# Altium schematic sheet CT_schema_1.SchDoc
size 395 x 258 mm
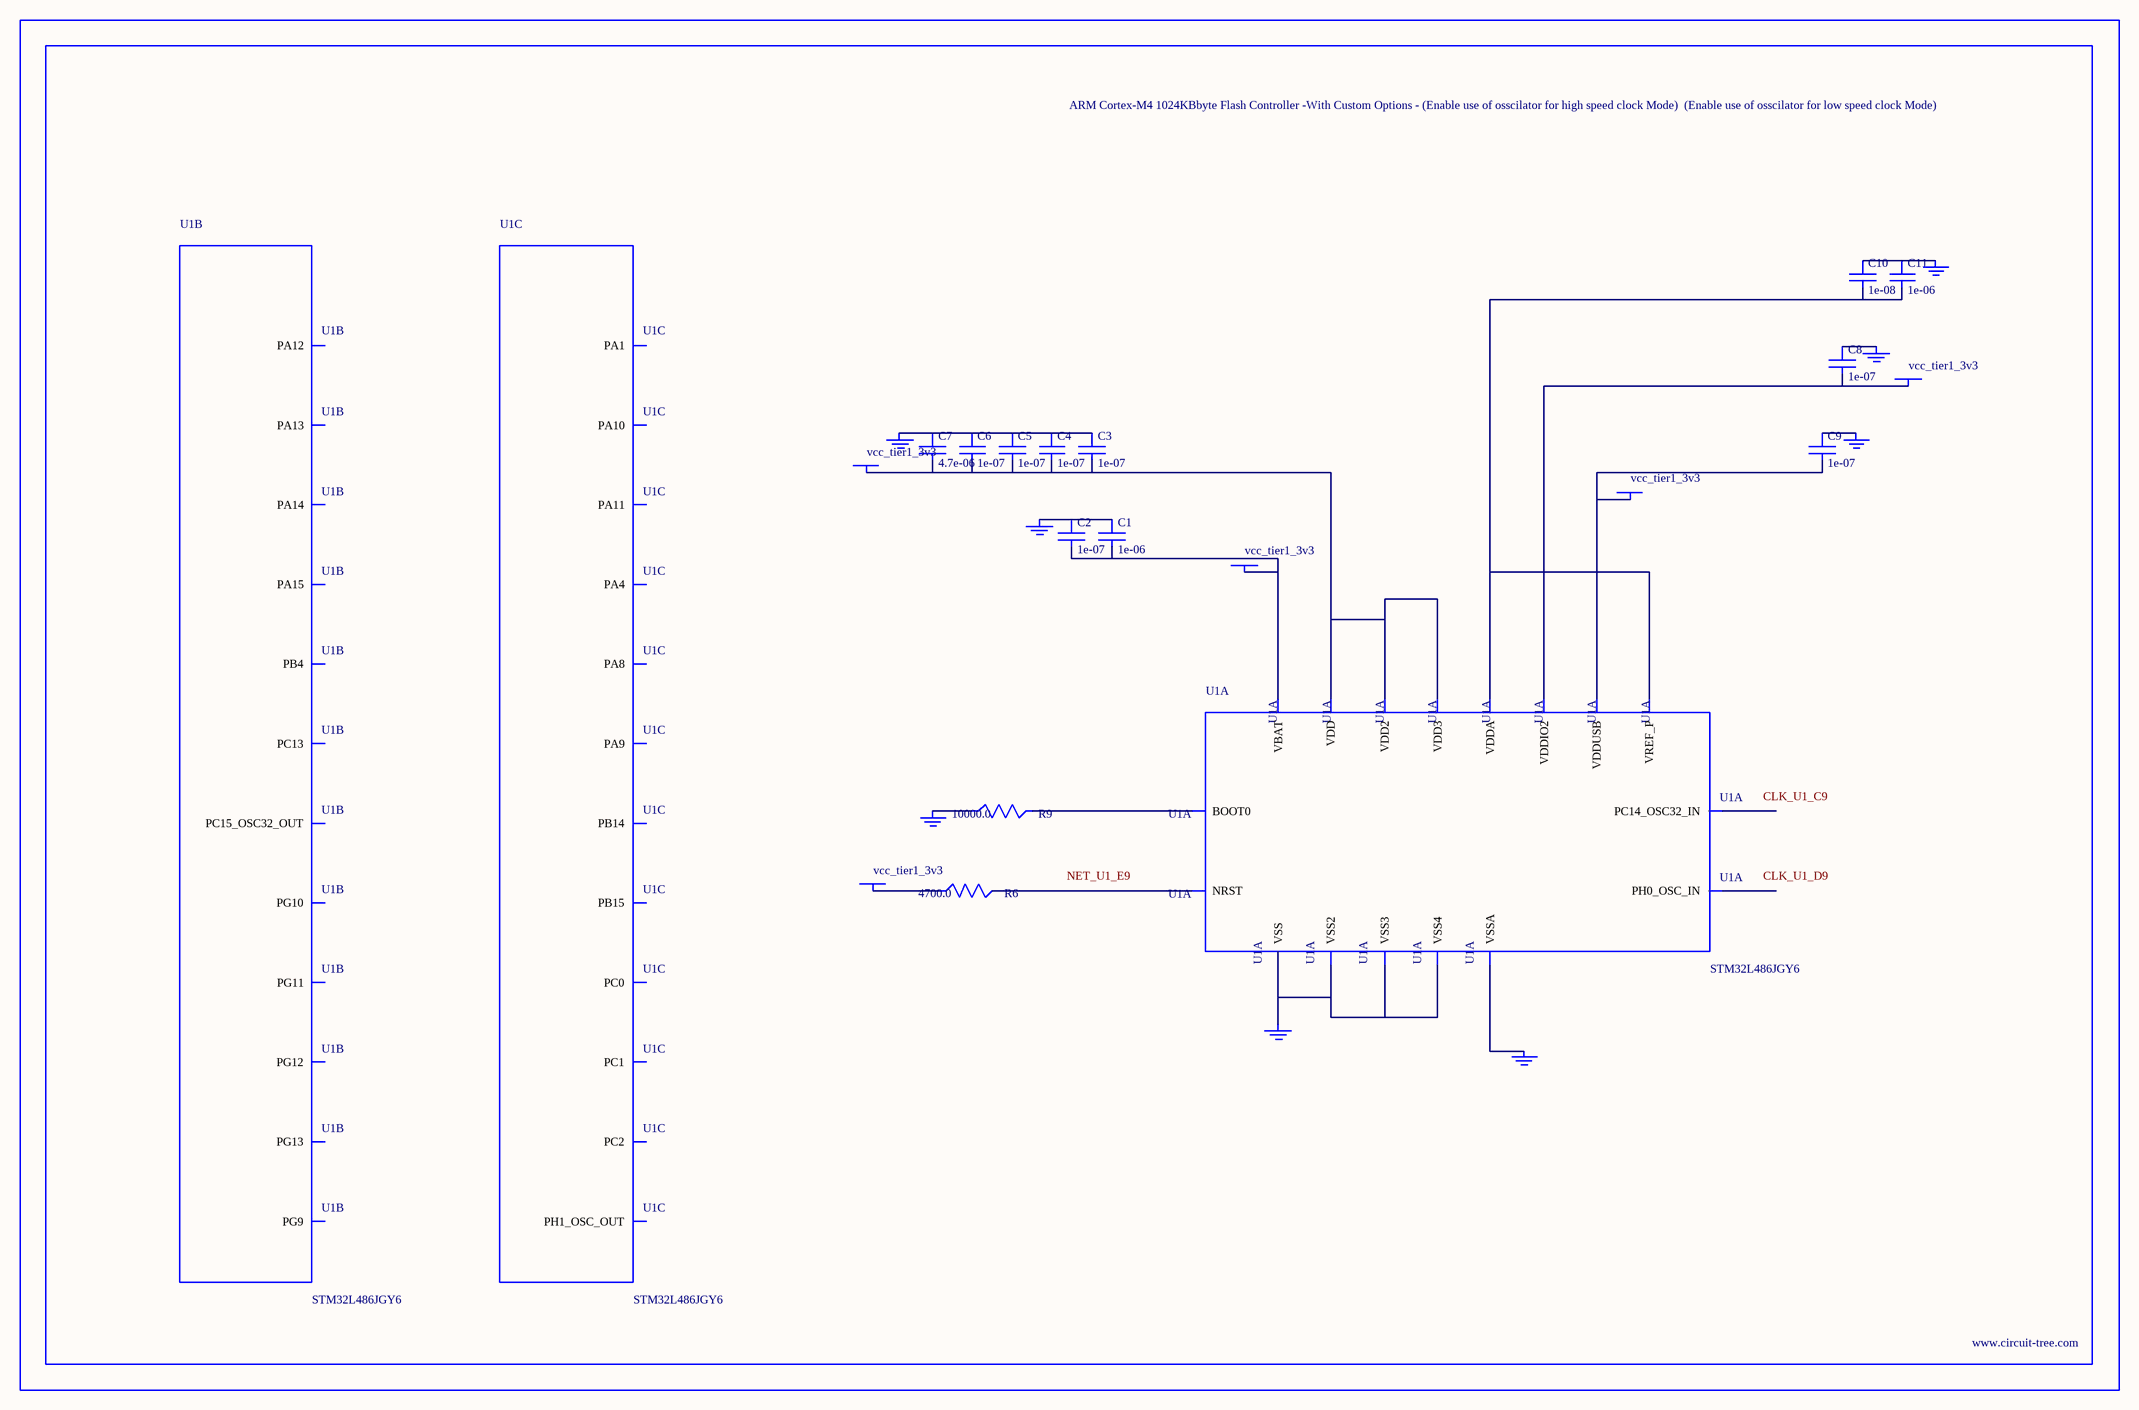
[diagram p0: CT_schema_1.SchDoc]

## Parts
BORDER0  (no value)
C1  1e-06  [C0603]
C2  1e-07  [C0603]
C3  1e-07  [C0603]
C4  1e-07  [C0603]
C5  1e-07  [C0603]
C6  1e-07  [C0603]
C7  4.7e-06  [C0603]
C8  1e-07  [C0603]
C9  1e-07  [C0603]
C10  1e-08  [C0603]
C11  1e-06  [C0603]
GND_INSTANCE_0_0  (no value)
GND_INSTANCE_0_1  (no value)
GND_INSTANCE_0_2  (no value)
GND_INSTANCE_0_3  (no value)
GND_INSTANCE_0_4  (no value)
GND_INSTANCE_0_5  (no value)
GND_INSTANCE_0_6  (no value)
GND_INSTANCE_0_7  (no value)
POWER_INSTANCE_0_0  vcc_tier1_3v3
POWER_INSTANCE_0_1  vcc_tier1_3v3
POWER_INSTANCE_0_2  vcc_tier1_3v3
POWER_INSTANCE_0_3  vcc_tier1_3v3
POWER_INSTANCE_0_4  vcc_tier1_3v3
R6  4700.0  [R0603]
R9  10000.0  [R0603]
U1  STM32L486JGY6  [WLCSP72]  (parts A,B,C of 7)

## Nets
NetC1_1: C1.1 C2.1 GND_INSTANCE_0_0.0(GND)
NetC1_2: C1.2 C2.2 POWER_INSTANCE_0_0.0(PWR) U1.B9(VBAT)
NetC3_1: C3.1 C4.1 C5.1 C6.1 C7.1 GND_INSTANCE_0_1.0(GND)
NetC3_2: C3.2 C4.2 C5.2 C6.2 C7.2 POWER_INSTANCE_0_1.0(PWR) U1.A9(VDD) U1.J1(VDD2) U1.J8(VDD3)
NetC8_1: C8.1 GND_INSTANCE_0_2.0(GND)
NetC8_2: C8.2 POWER_INSTANCE_0_2.0(PWR) U1.B6(VDDIO2)
NetC9_1: C9.1 GND_INSTANCE_0_4.0(GND)
NetC9_2: C9.2 POWER_INSTANCE_0_3.0(PWR) U1.A1(VDDUSB)
NetC10_1: C10.1 C11.1 GND_INSTANCE_0_5.0(GND)
NetC10_2: C10.2 C11.2 U1.G8(VREF_P) U1.H9(VDDA)
NetGND_INSTANCE_0_3_0: GND_INSTANCE_0_3.0(GND) R9.1
NetGND_INSTANCE_0_6_0: GND_INSTANCE_0_6.0(GND) U1.G9(VSSA)
NetGND_INSTANCE_0_7_0: GND_INSTANCE_0_7.0(GND) U1.A8(VSS) U1.B1(VSS2) U1.J2(VSS3) U1.J9(VSS4)
NetPOWER_INSTANCE_0_4_0: POWER_INSTANCE_0_4.0(PWR) R6.1
NetR6_2: R6.2 U1.E9(NRST)
NetR9_2: R9.2 U1.D7(BOOT0)

Not connected (* = marked no-connect by the designer): U1 A2(PA15) A4(PG9) B2(PA14) B4(PG10) B5(PG13) B8(PC13) C1(PA12) C2(PA13) C4(PG11) C5(PG12) C6(PB4) C8(PC15_OSC32_OUT) C9(PC14_OSC32_IN) D1(PA11) D2(PA10) D8(PH1_OSC_OUT) D9(PH0_OSC_IN) E2(PA8) E3(PA9) F7(PC2) F8(PC1) F9(PC0) G1(PB15) G2(PB14) G4(PA1) G5(PA4)

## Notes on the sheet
- Labels drawn without touching a wire or pin: CLK_U1_C9, CLK_U1_D9, NET_U1_E9

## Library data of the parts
BORDER0 = BORDER_PAGE0
C1 C11 = C0603C105K3RACTU
C2-C6 C8 C9 = 06035C104K4Z2A
C7 = GRM188R6YA475KE15D
C10 = 06035C103K4Z2A
GND_INSTANCE_0_0-GND_INSTANCE_0_7 = GND
POWER_INSTANCE_0_0-POWER_INSTANCE_0_4 = PWR
R6 = RC0603JR-074K7L
R9 = RC0603JR-0710KL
